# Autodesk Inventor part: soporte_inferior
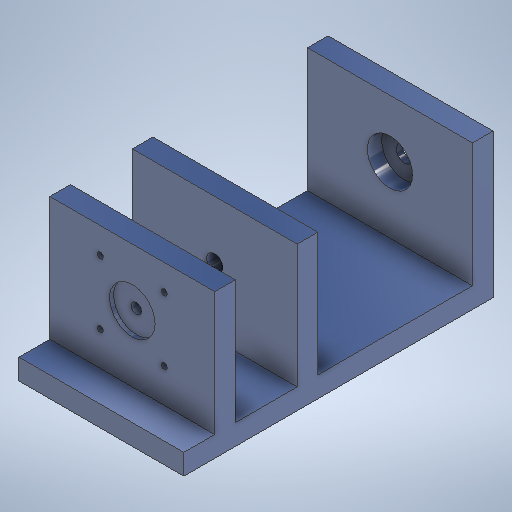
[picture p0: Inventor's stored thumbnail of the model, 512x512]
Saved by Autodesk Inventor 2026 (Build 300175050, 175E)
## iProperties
Created: 2025-06
Part Number: soporte_inferior
Material: Genérico
Document SubType Name: Modeling
Designer: piero
Density: 1 g/cm^3
Appearance: Valor por defecto
Author: piero
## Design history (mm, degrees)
sketch "Boceto1"
  geometry: L1 (0, 0)-(80, 0); L2 (80, 0)-(80, -150); L3 (80, -150)-(0, -150); L4 (0, -150)-(0, 0); L5 (80, -150)-(0, -150); L6 (0, -150)-(0, -140); L7 (0, -140)-(80, -140); L8 (80, -140)-(80, -150); L9 (80, -65)-(0, -65); L10 (0, -65)-(0, -55); L11 (0, -55)-(80, -55); L12 (80, -55)-(80, -65); L13 (80, -25)-(0, -25); L14 (0, -25)-(0, -15); L15 (0, -15)-(80, -15); L16 (80, -15)-(80, -25); 8 further points
  constraints: 32 end point, 8 parallel, 4 horizontal, 4 perpendicular, 2 point on line
  dimensions: "d0" = 80 distance of L2.end L3.end; "d1" = 150 distance of L1.end L2.end; "d4" = 80 distance of L6.end L7.end; "d5" = 10 distance of L5.end L6.end; "d6" = 80 distance of L10.end L11.end; "d7" = 10 distance of L9.end L10.end; "d8" = 80 distance of L14.end L15.end; "d9" = 10 distance of L13.end L14.end; "d17" = 75 distance between parallel lines of L9 L7; "d19" = 30 distance between parallel lines of L11 L13
extrude "Extrusión1" new body sketch "Boceto1" distance "d2" = 10; taper "d3" = 0 deg
extrude "Extrusión2" join sketch "Boceto1" distance "d10" = 70; taper "d11" = 0 deg
sketch "Boceto3"
  geometry: L1 (0, 0)-(0, 70) reference; L2 (0, 70)-(80, 70) reference; L3 (80, 10)-(0, 10) reference; C1 r 4 at (40, 42); C2 r 11 at (40, 42)
  constraints: 2 centre point, 1 coincident
  dimensions: "d12" = 8 diameter of C1; "d13" = 40 distance from line of C1.centre L1; "d18" = 32 distance from line of L3 C1.centre; "d54" = 22 diameter of C2
extrude "Extrusión3" cut sketch "Boceto3" distance "d15" = 10; taper "d16" = 0 deg
sketch "Boceto4"
  geometry: C1 r 4 at (40, 32) reference; C2 r 2.5 at (40, 32); C3 r 11.05 at (40, 32); C4 r 1.5 at (24.5, 47.5); C5 r 1.5 at (55.5, 47.5); C6 r 1.5 at (24.501, 16.5); C7 r 1.5 at (55.499, 16.5); 1 further point
  constraints: 6 centre point, 2 coincident
  dimensions: "d20" = 5 diameter of C2; "d21" = 22.1 diameter of C3; "d26" = 3 diameter of C4; "d27" = 21.92 distance of C3.centre C4.centre; "d28" = 3 diameter of C5; "d29" = 21.92 distance of C3.centre C5.centre; "d30" = 3 diameter of C6; "d31" = 3 diameter of C7; "d32" = 21.92 distance of C3.centre C6.centre; "d33" = 21.92 distance of C2.centre C7.centre; "d47" = 0 vertical distance of C5.centre C4.centre; "d48" = 31 distance of C5.centre C4.centre; "d51" = 0 vertical distance of C7.centre C6.centre; "d53" = 31 distance of C6.centre C4.centre
extrude "Extrusión4" cut sketch "Boceto4" distance "d22" = 10; taper "d23" = 0 deg
extrude "Extrusión5" cut sketch "Boceto4" distance "d24" = 10; taper "d25" = 0 deg
extrude "Extrusión6" cut sketch "Boceto4" distance "d34" = 2; taper "d35" = 0 deg
feature "Rosca1" dims "d36" = 10, "d37" = 0
feature "Rosca2" dims "d38" = 10, "d39" = 0
feature "Rosca3" dims "d40" = 10, "d41" = 0
feature "Rosca4" dims "d42" = 10, "d43" = 0
sketch "Boceto5"
  geometry: C1 r 2.5 at (40, 32) reference; C2 r 4 at (40, 32); 1 further point
  constraints: 1 centre point, 1 coincident
  dimensions: "d44" = 8 diameter of C2
extrude "Extrusión7" cut sketch "Boceto5" distance "d45" = 10; taper "d46" = 0 deg
sketch "Boceto6"
  geometry: C1 r 2.5 at (40, 32) reference; C2 r 11 at (40, 32); 1 further point
  constraints: 1 centre point, 1 coincident
  dimensions: "d55" = 22 diameter of C2
extrude "Extrusión8" cut sketch "Boceto6" distance "d56" = 7; taper "d57" = 0 deg
node "Sólido1"
